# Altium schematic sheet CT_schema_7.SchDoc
size 287 x 160 mm
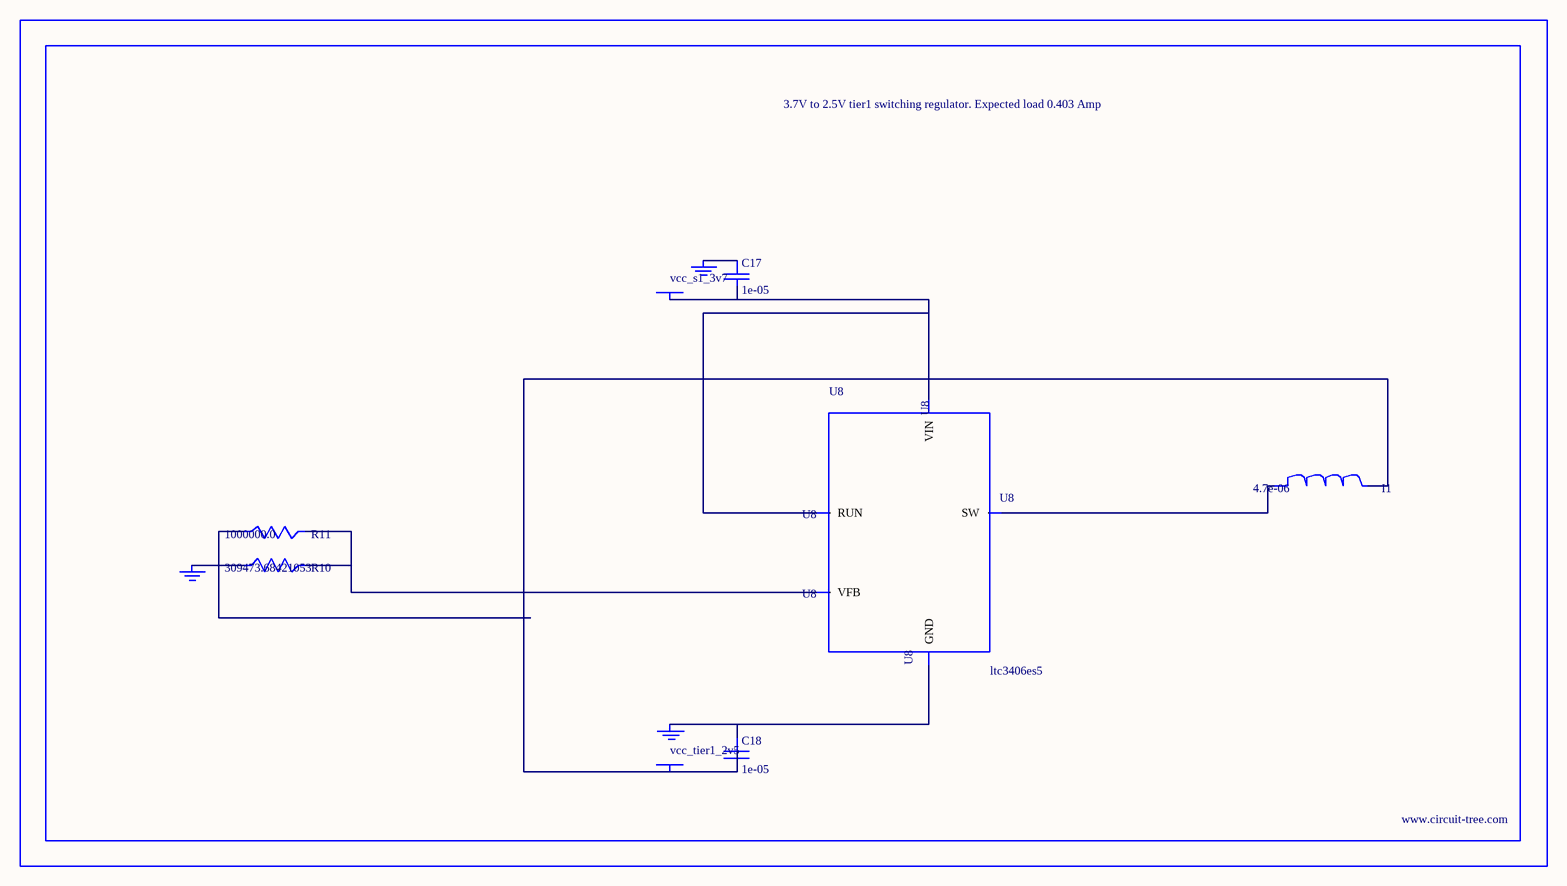
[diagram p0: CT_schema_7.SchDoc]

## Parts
BORDER6  (no value)
C17  1e-05  [C0805]
C18  1e-05  [C0805]
GND_INSTANCE_6_0  (no value)
GND_INSTANCE_6_1  (no value)
GND_INSTANCE_6_2  (no value)
I1  4.7e-06  [L0805]
POWER_INSTANCE_6_0  vcc_tier1_2v5
POWER_INSTANCE_6_1  vcc_s1_3v7
R10  309473.68421053  [R0603]
R11  1000000.0  [R0603]
U8  ltc3406es5  [TSOT-23-5]

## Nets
NetC17_1: C17.1 GND_INSTANCE_6_1.0(GND)
NetC17_2: C17.2 POWER_INSTANCE_6_1.0(PWR) U8.1(RUN) U8.4(VIN)
NetC18_1: C18.1 GND_INSTANCE_6_0.0(GND) U8.2(GND)
NetC18_2: C18.2 I1.2 POWER_INSTANCE_6_0.0(PWR) R11.1
NetGND_INSTANCE_6_2_0: GND_INSTANCE_6_2.0(GND) R10.1
NetI1_1: I1.1 U8.3(SW)
NetR10_2: R10.2 R11.2 U8.5(VFB)

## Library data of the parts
BORDER6 = BORDER_PAGE6
C17 C18 = C0805C106K8RACTU
GND_INSTANCE_6_0-GND_INSTANCE_6_2 = GND
I1 = L0805C4R7MDWST
POWER_INSTANCE_6_0 POWER_INSTANCE_6_1 = PWR
R10 = R10
R11 = RC0603JR-071ML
